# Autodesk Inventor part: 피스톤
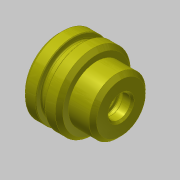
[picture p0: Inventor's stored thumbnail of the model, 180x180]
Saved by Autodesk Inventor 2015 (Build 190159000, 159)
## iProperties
Created: 2020-02
Part Number: 피스톤
Material: 강철, 탄소
Document SubType Name: Modeling
Designer: mduedu
Density: 1 g/cm^3
Appearance: 노란색
Author: mduedu
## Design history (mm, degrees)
sketch "스케치1"
  geometry: L1 (0, 0)-(20, 0); L2 (20, 0)-(20, 20); L3 (20, 20)-(0, 20); L4 (0, 20)-(0, 0); L5 (20, 0)-(33, 0); L6 (33, 0)-(33, 15); L7 (33, 15)-(20, 15); L8 (20, 15)-(20, 0)
  constraints: 16 end point, 4 parallel, 2 horizontal, 2 perpendicular
  dimensions: "d0" = 33 distance between parallel lines of L6 L4; "d2" = 20 distance of L2.end L3.end; "d3" = 40 diameter of L3 L1; "d4" = 30 diameter of L7 L5
revolve "회전1" sketch "스케치1" stored, may be unused: angle "d5" = 90 deg
sketch "스케치2"
  geometry: L1 (0, -20)-(0, 20) reference; L2 (0, 20)-(20, 20) reference; L3 (20, 20)-(20, 15) reference; L4 (20, 15)-(33, 15) reference; L5 (33, 15)-(33, -15) reference; L6 (33, -15)-(20, -15) reference; L7 (20, -15)-(20, -20) reference; L8 (20, -20)-(0, -20) reference; L9 (0, 0)-(20, 0); L10 (20, 0)-(20, 11); L11 (20, 11)-(0, 11); L12 (0, 11)-(0, 0); L13 (33, 0)-(20, 0); L14 (20, 0)-(20, 6); L15 (20, 6)-(33, 6); L16 (33, 6)-(33, 0)
  constraints: 16 end point, 4 parallel, 2 horizontal, 2 perpendicular, 1 midpoint, 1 point on line
  dimensions: "d6" = 22 diameter of L11 L9; "d8" = 12 diameter of L15 L13; "d9" = 20 distance of L10.end L11.end
revolve "회전2" sketch "스케치2" stored, may be unused: angle "d10" = 90 deg
chamfer "모따기1" distance "d11" = 2; stored, may be unused: second distance "d12" = 2, angle "d13" = 45 deg
sketch "스케치3"
  geometry: L1 (20, -11)-(20, -6) reference; L2 (20, -6)-(33, -6) reference; L3 (33, -6)-(33, -13) reference; L4 (33, -13)-(31, -15) reference; L5 (31, -15)-(20, -15) reference; L6 (20, -15)-(20, -18) reference; L7 (20, -18)-(18, -20) reference; L8 (18, -20)-(2, -20) reference; L9 (2, -20)-(0, -18) reference; L10 (0, -18)-(0, -11) reference; L11 (0, -11)-(20, -11) reference; L12 (20, 6)-(20, 11) reference; L13 (20, 11)-(0, 11) reference; L14 (0, 11)-(0, 18) reference; L15 (0, 18)-(2, 20) reference; L16 (2, 20)-(18, 20) reference; L17 (18, 20)-(20, 18) reference; L18 (20, 18)-(20, 15) reference; L19 (20, 15)-(31, 15) reference; L20 (31, 15)-(33, 13) reference; L21 (33, 13)-(33, 6) reference; L22 (33, 6)-(20, 6) reference; L23 (7.65, 20)-(12.35, 20); L24 (12.35, 20)-(12.35, 17); L25 (12.35, 17)-(7.65, 17); L26 (7.65, 17)-(7.65, 20); L27 (24.4, 6)-(27.6, 6); L28 (27.6, 6)-(27.6, 8); L29 (27.6, 8)-(24.4, 8); L30 (24.4, 8)-(24.4, 6); L31 (10, 17)-(10, 20); L32 (26, 6)-(26, 8); L33 (-6.6, 0)-(39.6, 0) reference; 1 further point
  constraints: 20 end point, 4 midpoint, 4 parallel, 2 horizontal, 2 perpendicular, 2 point on line
  dimensions: "d14" = 10 distance between parallel lines of L31 L14; "d15" = 7 distance between parallel lines of L32 L21; "d16" = 4.7 distance between parallel lines of L24 L26; "d17" = 34 diameter of L25 L33; "d18" = 16 diameter of L29 L33; "d19" = 3.2 distance of L28.end L29.end
revolve "회전3" sketch "스케치3" stored, may be unused: angle "d20" = 90 deg
fillet "모깎기1" dims "d21" = 0.8
fillet "모깎기2" dims "d22" = 0.4
chamfer "모따기2" distance "d23" = 0.3; stored, may be unused: second distance "d24" = 2, angle "d25" = 45 deg
chamfer "모따기3" distance "d26" = 0.3; stored, may be unused: second distance "d27" = 2, angle "d28" = 45 deg
chamfer "모따기4" distance "d29" = 1; stored, may be unused: second distance "d30" = 2, angle "d31" = 45 deg
node "솔리드1"
node "절단 모서리 투영1"
node "절단 모서리 투영2"
